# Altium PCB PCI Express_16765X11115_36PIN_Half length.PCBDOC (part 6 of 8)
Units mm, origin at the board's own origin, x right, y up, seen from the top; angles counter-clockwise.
Board outline 178 x 110.97 mm, 10 copper layers (Top Layer, Int1 (GND), Int2 (Sign), Int3 (Sign), Int4 (PWR), Int5 (GND), Int6 (Sign), Int7 (Sign), Int8 (GND), Bottom Layer), stack 1.429 mm thick; 528 components, 525 nets, 2272 pads, 1491 vias.
Unrouted connection lines stored in the file: 373.
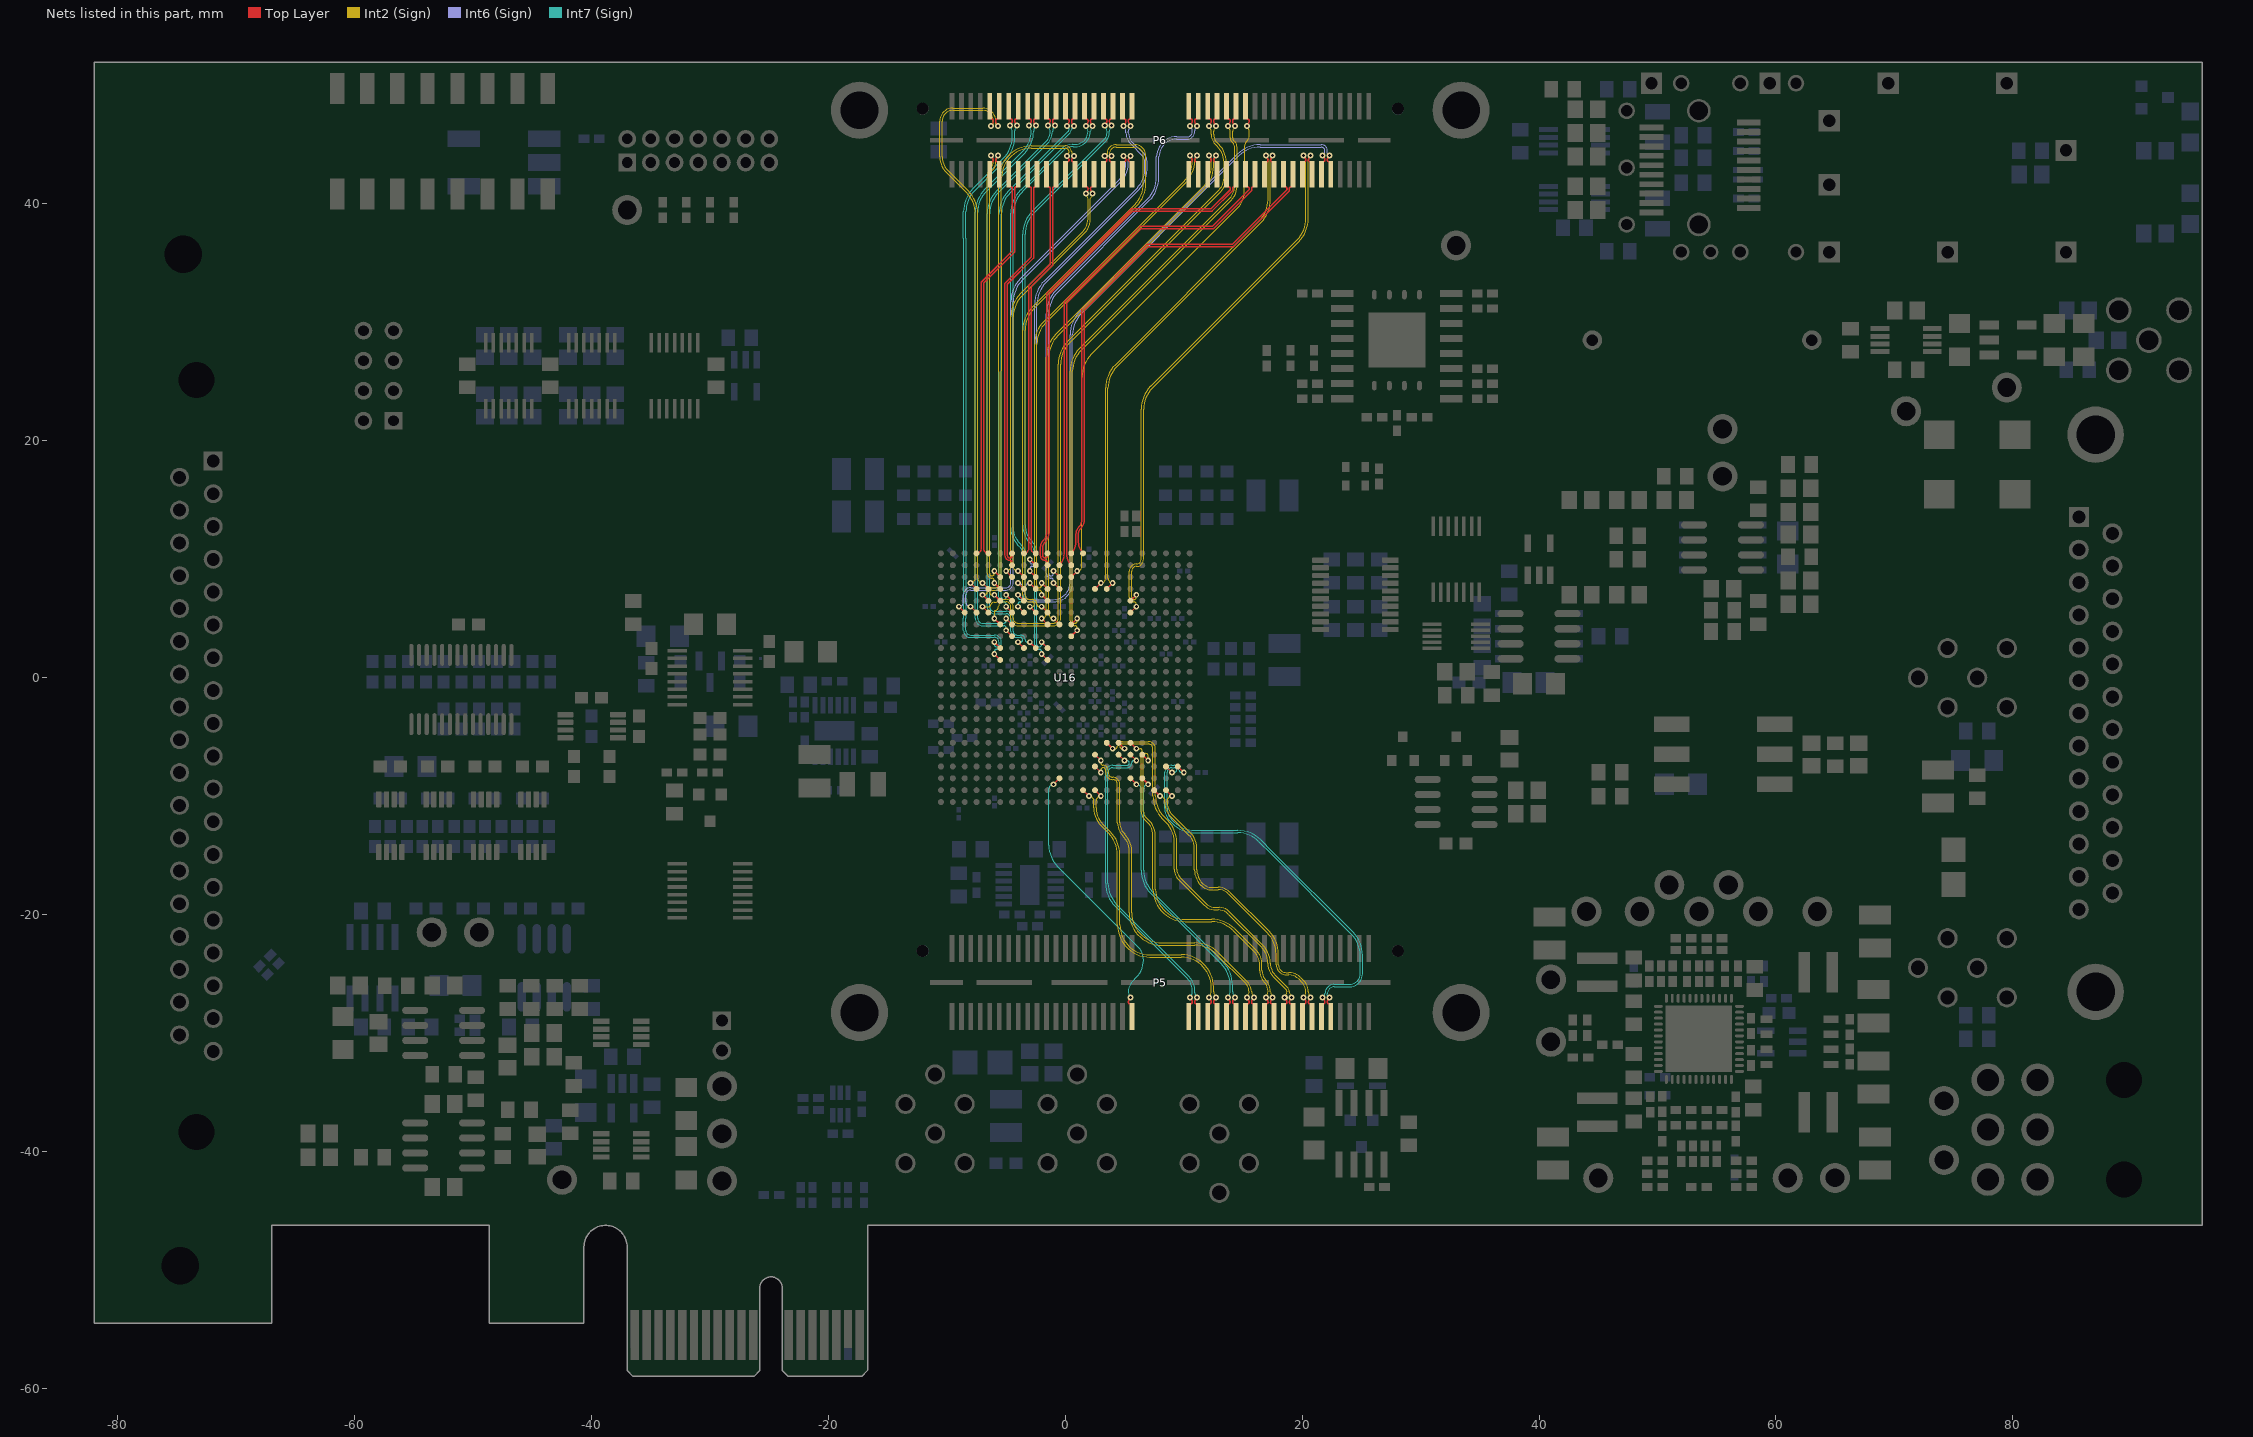
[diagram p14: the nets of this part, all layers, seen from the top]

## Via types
v1: diameter 0.483, hole 0.254, Top Layer to Bottom Layer, tented both sides, 740 vias
v2: diameter 0.508, hole 0.254, Top Layer to Bottom Layer, tented both sides, 302 vias
v3: diameter 0.406, hole 0.254, Top Layer to Bottom Layer, tented both sides, 267 vias
v4: diameter 0.305, hole 0.152, Top Layer to Bottom Layer, tented both sides, 95 vias
v5: diameter 0.5, hole 0.254, Top Layer to Bottom Layer, tented both sides, 50 vias
v6: diameter 0.45, hole 0.254, Top Layer to Bottom Layer, tented both sides, 23 vias
v7: diameter 0.6, hole 0.254, Top Layer to Bottom Layer, tented both sides, 14 vias

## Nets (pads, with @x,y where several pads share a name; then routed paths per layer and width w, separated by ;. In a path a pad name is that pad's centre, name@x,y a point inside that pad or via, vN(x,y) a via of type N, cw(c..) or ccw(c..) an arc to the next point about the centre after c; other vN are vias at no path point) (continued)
S17_32.S24_P: P5.39 U16.L3 | length 24.3
  Top Layer w0.127: v1(-1,-9) U16.L3@-0.5,-8.5 ; v2(5.512,-27) cw(c5.333,-27) 5.46,-27.127 5.417,-27.17 ccw(c5.647,-27.4) 5.322,-27.4 ccw(c5.474,-27.4) 5.366,-27.508 ccw(c5.438,-27.436) 5.438,-27.538 cw(c5.438,-27.64) 5.51,-27.568 5.55,-27.608 cw(c5.382,-27.776) 5.62,-27.776 P5.39@5.62,-28.605
  Int7 (Sign) w0.076: v1(-1,-9) ccw(c-1,-9.398) -1.398,-9.398 -1.398,-14.149 ccw(c1.142,-14.149) -0.654,-15.946 6.152,-22.752 cw(c5.063,-23.841) 6.603,-23.841 6.603,-23.844 cw(c4.544,-23.844) 6,-25.3 5.719,-25.581 ccw(c6.678,-26.54) 5.322,-26.54 ccw(c5.803,-26.54) 5.463,-26.88 cw(c5.343,-27) v2(5.512,-27)
S17_32.S25_N: P5.43 U16.U5 | length 27.4
  Top Layer w0.127: U16.U5@5.5,-6.5 v1(6,-7) ; v2(11.112,-27) cw(c10.932,-27) 11.059,-27.127 11.017,-27.17 ccw(c11.247,-27.4) 10.922,-27.4 ccw(c11.074,-27.4) 10.966,-27.508 ccw(c11.038,-27.436) 11.038,-27.538 cw(c11.038,-27.64) 11.11,-27.568 11.15,-27.608 cw(c10.981,-27.776) 11.22,-27.776 P5.43@11.22,-28.605
  Int7 (Sign) w0.076: v1(6,-7) 5.802,-7 ccw(c5.802,-7.2) 5.602,-7.2 cw(c5.198,-7.2) 5.198,-7.603 4,-7.603 ccw(c4,-8.003) 3.6,-8.003 3.6,-17.361 ccw(c6.14,-17.361) 4.344,-19.157 10.445,-25.257 cw(c9.293,-26.409) 10.922,-26.409 10.922,-26.6 ccw(c11.258,-26.6) 11.02,-26.838 11.063,-26.88 cw(c10.943,-27) v2(11.112,-27)
S17_32.S25_P: P5.41 U16.T5 | length 27.4
  Top Layer w0.127: U16.T5@4.5,-6.5 v1(5,-7) ; P5.41@10.42,-28.605 10.42,-27.776 cw(c10.658,-27.776) 10.49,-27.608 10.53,-27.568 cw(c10.602,-27.64) 10.602,-27.538 ccw(c10.602,-27.436) 10.674,-27.508 ccw(c10.566,-27.4) 10.718,-27.4 ccw(c10.393,-27.4) 10.623,-27.17 10.58,-27.127 cw(c10.707,-27) v2(10.528,-27)
  Int7 (Sign) w0.076: v1(5,-7) 5.198,-7 cw(c5.198,-7.2) 5.398,-7.2 cw(c5.198,-7.2) 5.198,-7.4 4,-7.4 ccw(c4,-8.003) 3.397,-8.003 3.397,-17.361 ccw(c6.139,-17.361) 4.2,-19.3 10.3,-25.4 cw(c9.29,-26.41) 10.718,-26.41 10.718,-26.6 cw(c10.382,-26.6) 10.62,-26.838 10.577,-26.88 ccw(c10.697,-27) v2(10.528,-27)
S17_32.S26_N: P5.45 U16.N2 | length 26.1
  Top Layer w0.127: U16.N2@1.5,-9.5 v1(2,-10) ; P5.45@12.02,-28.605 12.02,-27.776 cw(c12.258,-27.776) 12.09,-27.608 12.13,-27.568 cw(c12.202,-27.64) 12.202,-27.538 ccw(c12.202,-27.436) 12.274,-27.508 ccw(c12.166,-27.4) 12.318,-27.4 ccw(c11.993,-27.4) 12.223,-27.17 12.18,-27.127 cw(c12.307,-27) v2(12.128,-27)
  Int2 (Sign) w0.076: v1(2,-10) cw(c2,-10.398) 2.398,-10.398 2.398,-11.001 ccw(c4.535,-11.001) 3.024,-12.512 3.656,-13.143 cw(c1.86,-14.939) 4.4,-14.939 4.4,-20.857 ccw(c7.143,-20.857) 7.143,-23.6 9.778,-23.6 cw(c9.778,-26.14) 12.318,-26.14 12.318,-26.54 cw(c11.837,-26.54) 12.177,-26.88 ccw(c12.297,-27) v2(12.128,-27)
S17_32.S26_P: P5.47 U16.P2 | length 26.1
  Top Layer w0.127: U16.P2@2.5,-9.5 v1(3,-10) ; v2(12.712,-27) cw(c12.532,-27) 12.659,-27.127 12.617,-27.17 ccw(c12.847,-27.4) 12.521,-27.4 ccw(c12.673,-27.4) 12.566,-27.508 ccw(c12.638,-27.436) 12.638,-27.538 cw(c12.638,-27.64) 12.71,-27.568 12.75,-27.608 cw(c12.581,-27.776) 12.82,-27.776 P5.47@12.82,-28.605
  Int2 (Sign) w0.076: v1(3,-10) ccw(c3,-10.398) 2.602,-10.398 2.602,-11 ccw(c4.537,-11) 3.168,-12.368 3.802,-13.002 cw(c1.866,-14.937) 4.603,-14.937 4.603,-20.857 ccw(c7.143,-20.857) 7.143,-23.397 9.778,-23.397 cw(c9.778,-26.14) 12.521,-26.14 12.521,-26.54 ccw(c13.003,-26.54) 12.662,-26.88 cw(c12.543,-27) v2(12.712,-27)
S17_32.S27_N: P5.51 U16.V3 | length 23.7
  Top Layer w0.127: U16.V3@6.5,-8.5 v1(7,-9) ; v2(14.312,-27) cw(c14.132,-27) 14.259,-27.127 14.217,-27.17 ccw(c14.447,-27.4) 14.122,-27.4 ccw(c14.274,-27.4) 14.166,-27.508 ccw(c14.238,-27.436) 14.238,-27.538 cw(c14.238,-27.64) 14.31,-27.568 14.35,-27.608 cw(c14.181,-27.776) 14.42,-27.776 P5.51@14.42,-28.605
  Int7 (Sign) w0.076: v1(7,-9) ccw(c7,-9.398) 6.602,-9.398 6.602,-16.262 ccw(c9.142,-16.262) 7.346,-18.058 13.319,-24.031 cw(c11.38,-25.97) 14.122,-25.97 14.122,-26.54 ccw(c14.603,-26.54) 14.262,-26.88 cw(c14.143,-27) v2(14.312,-27)
S17_32.S27_P: P5.49 U16.U3 | length 23.7
  Top Layer w0.127: U16.U3@5.5,-8.5 v1(6,-9) ; P5.49@13.62,-28.605 13.62,-27.776 cw(c13.858,-27.776) 13.69,-27.608 13.73,-27.568 cw(c13.802,-27.64) 13.802,-27.538 ccw(c13.802,-27.436) 13.874,-27.508 ccw(c13.766,-27.4) 13.918,-27.4 ccw(c13.593,-27.4) 13.823,-27.17 13.78,-27.127 cw(c13.907,-27) v2(13.728,-27)
  Int7 (Sign) w0.076: v1(6,-9) cw(c6,-9.398) 6.398,-9.398 6.398,-16.263 ccw(c9.14,-16.263) 7.201,-18.201 13.174,-24.174 cw(c11.378,-25.97) 13.918,-25.97 13.918,-26.54 cw(c13.437,-26.54) 13.777,-26.88 ccw(c13.897,-27) v2(13.728,-27)
S17_32.S28_N: P5.53 U16.P4 | length 30.2
  Top Layer w0.127: U16.P4@2.5,-7.5 v1(3,-8) ; P5.53@15.22,-28.605 15.22,-27.776 cw(c15.458,-27.776) 15.289,-27.608 15.33,-27.568 cw(c15.402,-27.64) 15.402,-27.538 ccw(c15.402,-27.436) 15.474,-27.508 ccw(c15.366,-27.4) 15.518,-27.4 ccw(c15.193,-27.4) 15.423,-27.17 15.38,-27.127 cw(c15.507,-27) v2(15.328,-27)
  Int2 (Sign) w0.076: v1(3,-8) 3,-7.802 cw(c3.2,-7.802) 3.2,-7.602 cw(c3.2,-7.802) 3.4,-7.802 3.4,-8.003 ccw(c4,-8.003) 4,-8.603 4.003,-8.603 cw(c4.003,-9) 4.4,-9 4.4,-12.244 ccw(c5.953,-12.244) 4.855,-13.342 cw(c3.539,-14.658) 4.856,-13.344 cw(c3.539,-14.658) 5.4,-14.658 5.4,-19.857 ccw(c8.143,-19.857) 8.143,-22.6 10.948,-22.6 cw(c10.948,-25.14) 12.744,-23.344 15.22,-25.82 cw(c14.499,-26.54) 15.518,-26.54 cw(c15.037,-26.54) 15.377,-26.88 ccw(c15.497,-27) v2(15.328,-27)
S17_32.S28_P: P5.55 U16.P5 | length 30.5
  Top Layer w0.127: U16.P5@2.5,-6.5 v1(3,-7) ; v2(15.912,-27) cw(c15.732,-27) 15.859,-27.127 15.817,-27.17 ccw(c16.046,-27.4) 15.721,-27.4 ccw(c15.873,-27.4) 15.766,-27.508 ccw(c15.838,-27.436) 15.838,-27.538 cw(c15.838,-27.64) 15.91,-27.568 15.95,-27.608 cw(c15.781,-27.776) 16.02,-27.776 P5.55@16.02,-28.605
  Int2 (Sign) w0.076: v1(3,-7) 3,-7.198 ccw(c3.2,-7.198) 3.2,-7.398 cw(c3.2,-7.802) 3.603,-7.802 3.603,-8.003 ccw(c4,-8.003) 4,-8.4 4.003,-8.4 cw(c4.003,-9) 4.603,-9 4.603,-12.242 ccw(c5.958,-12.242) 5,-13.2 5.002,-13.202 cw(c3.549,-14.654) 5.003,-13.203 cw(c3.549,-14.654) 5.603,-14.654 5.603,-19.857 ccw(c8.143,-19.857) 8.143,-22.397 10.949,-22.397 cw(c10.949,-25.138) 12.887,-23.2 15.365,-25.677 cw(c14.504,-26.538) 15.721,-26.538 15.721,-26.54 ccw(c16.203,-26.54) 15.862,-26.88 cw(c15.743,-27) v2(15.912,-27)
S17_32.S29_N: P5.59 U16.V5 | length 30.4
  Top Layer w0.127: U16.V5@6.5,-6.5 v1(7,-7) ; v2(17.512,-27) cw(c17.332,-27) 17.459,-27.127 17.417,-27.17 ccw(c17.647,-27.4) 17.321,-27.4 ccw(c17.474,-27.4) 17.366,-27.508 ccw(c17.438,-27.436) 17.438,-27.538 cw(c17.438,-27.64) 17.51,-27.568 17.55,-27.608 cw(c17.381,-27.776) 17.62,-27.776 P5.59@17.62,-28.605
  Int2 (Sign) w0.076: v1(7,-7) 7,-6.6 ccw(c6.8,-6.6) 6.8,-6.4 ccw(c6.8,-6.6) 6.657,-6.46 ccw(c6.796,-6.598) 6.6,-6.598 6.6,-11.3 ccw(c7.324,-11.3) 6.812,-11.812 7.102,-12.102 ; 7.102,-12.102 cw(c5.893,-13.312) 7.603,-13.312 7.603,-17.857 ccw(c10.143,-17.857) 10.143,-20.397 12.349,-20.397 cw(c12.349,-23.138) 14.287,-21.2 16.187,-23.1 cw(c15.19,-24.097) 16.6,-24.097 16.6,-24.725 ccw(c17.776,-24.725) 16.945,-25.557 cw(c16.035,-26.467) 17.321,-26.467 17.321,-26.54 ccw(c17.803,-26.54) 17.462,-26.88 cw(c17.343,-27) v2(17.512,-27)
S17_32.S29_P: P5.57 U16.U6 | length 30.4
  Top Layer w0.127: U16.U6@5.5,-5.5 v1(6,-6) ; P5.57@16.82,-28.605 16.82,-27.776 cw(c17.058,-27.776) 16.89,-27.608 16.93,-27.568 cw(c17.002,-27.64) 17.002,-27.538 ccw(c17.002,-27.436) 17.074,-27.508 ccw(c16.966,-27.4) 17.118,-27.4 ccw(c16.793,-27.4) 17.023,-27.17 16.98,-27.127 cw(c17.107,-27) v2(16.928,-27)
  Int2 (Sign) w0.076: v1(6,-6) 6.3,-6 cw(c6.3,-6.2) 6.5,-6.2 6.5,-6.29 cw(c6.424,-6.29) 6.491,-6.326 6.464,-6.376 ccw(c6.796,-6.598) 6.397,-6.598 6.397,-6.649 6.397,-11.301 ccw(c7.323,-11.301) 6.668,-11.955 ; 6.668,-11.955 6.956,-12.244 cw(c5.885,-13.315) 7.4,-13.315 7.4,-17.857 ccw(c10.143,-17.857) 10.143,-20.6 12.348,-20.6 cw(c12.348,-23.14) 14.144,-21.344 16.041,-23.241 cw(c15.182,-24.1) 16.397,-24.1 16.397,-24.727 ccw(c17.773,-24.727) 16.8,-25.7 cw(c16.032,-26.468) 17.118,-26.468 17.118,-26.54 cw(c16.637,-26.54) 16.977,-26.88 ccw(c17.097,-27) v2(16.928,-27)
S17_32.S30_N: P5.61 U16.T6 | length 32.1
  Top Layer w0.127: U16.T6@4.5,-5.5 v1(5,-6) ; P5.61@18.42,-28.605 18.42,-27.776 cw(c18.658,-27.776) 18.489,-27.608 18.529,-27.568 cw(c18.601,-27.64) 18.601,-27.538 ccw(c18.601,-27.436) 18.673,-27.508 ccw(c18.566,-27.4) 18.718,-27.4 ccw(c18.393,-27.4) 18.623,-27.17 18.58,-27.127 cw(c18.707,-27) v2(18.528,-27)
  Int2 (Sign) w0.076: v1(5,-6) 4.802,-6 cw(c4.802,-5.8) 4.602,-5.8 cw(c4.802,-5.8) 4.802,-5.6 7,-5.6 cw(c7,-6) 7.4,-6 7.4,-9.964 ccw(c10.142,-9.964) 8.203,-11.903 8.5,-12.2 cw(c6.81,-13.89) 9.2,-13.89 9.2,-16.164 ccw(c10.464,-16.164) 9.57,-17.058 ; 9.572,-17.059 11.705,-19.192 ccw(c12.697,-18.199) 12.697,-19.603 12.9,-19.603 cw(c12.9,-20.818) 13.759,-19.959 16.528,-22.728 cw(c15.153,-24.102) 17.097,-24.1 cw(c15.153,-24.102) 17.097,-24.102 ccw(c18.736,-24.102) 17.577,-25.261 18.621,-26.305 cw(c18.385,-26.54) 18.718,-26.54 cw(c18.237,-26.54) 18.577,-26.88 ccw(c18.697,-27) v2(18.528,-27)
S17_32.S30_P: P5.63 U16.R6 | length 32.8
  Top Layer w0.127: U16.R6@3.5,-5.5 v1(4,-6) ; v2(19.112,-27) cw(c18.932,-27) 19.059,-27.127 19.017,-27.17 ccw(c19.246,-27.4) 18.921,-27.4 ccw(c19.073,-27.4) 18.966,-27.508 ccw(c19.038,-27.436) 19.038,-27.538 cw(c19.038,-27.64) 19.11,-27.568 19.15,-27.608 cw(c18.981,-27.776) 19.22,-27.776 P5.63@19.22,-28.605
  Int2 (Sign) w0.076: v1(4,-6) 4.198,-6 ccw(c4.198,-5.8) 4.398,-5.8 cw(c4.802,-5.8) 4.802,-5.397 7,-5.397 cw(c7,-6) 7.603,-6 7.603,-9.964 ccw(c10.143,-9.964) 8.347,-11.76 8.647,-12.059 cw(c6.821,-13.885) 9.403,-13.885 9.403,-16.162 ccw(c10.469,-16.162) 9.715,-16.915 11.846,-19.046 ccw(c12.7,-18.193) 12.7,-19.4 12.984,-19.4 cw(c12.984,-20.615) 13.843,-19.755 16.674,-22.587 cw(c15.163,-24.098) 17.3,-24.098 17.3,-24.1 ccw(c18.741,-24.1) 17.722,-25.119 18.765,-26.162 cw(c18.389,-26.539) 18.921,-26.539 18.921,-26.54 ccw(c19.403,-26.54) 19.062,-26.88 cw(c18.943,-27) v2(19.112,-27)
S17_32.S31_N: P5.67 U16.Y2 | length 25.7
  Top Layer w0.127: U16.Y2@8.5,-9.5 v1(9,-10) ; v2(20.712,-27) cw(c20.532,-27) 20.659,-27.127 20.617,-27.17 ccw(c20.847,-27.4) 20.521,-27.4 ccw(c20.674,-27.4) 20.566,-27.508 ccw(c20.638,-27.436) 20.638,-27.538 cw(c20.638,-27.64) 20.71,-27.568 20.75,-27.608 cw(c20.581,-27.776) 20.82,-27.776 P5.67@20.82,-28.605
  Int2 (Sign) w0.076: v1(9,-10) ccw(c9,-10.398) 8.602,-10.398 8.602,-10.5 ccw(c10.206,-10.5) 9.072,-11.635 10.586,-13.149 cw(c9.338,-14.397) 11.103,-14.397 11.103,-16.201 ccw(c12.799,-16.201) 11.6,-17.4 ccw(c12.324,-16.676) 12.324,-17.7 12.901,-17.7 cw(c12.901,-19.116) 13.902,-18.115 17.198,-21.411 cw(c15.263,-23.346) 18,-23.346 18,-24.245 ccw(c18.651,-24.245) 18.651,-24.897 18.878,-24.897 ; 18.884,-24.897 cw(c18.884,-26.248) 19.839,-25.292 20.123,-25.576 cw(c19.161,-26.538) 20.521,-26.535 cw(c19.161,-26.538) 20.521,-26.538 20.521,-26.54 ccw(c21.003,-26.54) 20.662,-26.88 cw(c20.543,-27) v2(20.712,-27)
S17_32.S31_P: P5.65 U16.W2 | length 25.7
  Top Layer w0.127: U16.W2@7.5,-9.5 v1(8,-10) ; P5.65@20.02,-28.605 20.02,-27.776 cw(c20.258,-27.776) 20.09,-27.608 20.13,-27.568 cw(c20.202,-27.64) 20.202,-27.538 ccw(c20.202,-27.436) 20.274,-27.508 ccw(c20.166,-27.4) 20.318,-27.4 ccw(c19.993,-27.4) 20.223,-27.17 20.18,-27.127 cw(c20.307,-27) v2(20.128,-27)
  Int2 (Sign) w0.076: v1(8,-10) cw(c8,-10.398) 8.398,-10.398 8.398,-10.501 ccw(c10.205,-10.501) 8.928,-11.778 10.441,-13.291 cw(c9.332,-14.4) 10.9,-14.4 10.9,-16.202 ccw(c12.796,-16.202) 11.455,-17.543 11.458,-17.545 ccw(c12.322,-16.68) 12.322,-17.903 12.9,-17.903 cw(c12.9,-19.118) 13.759,-18.259 17.053,-21.553 cw(c15.257,-23.349) 17.797,-23.349 17.797,-24.245 ccw(c18.651,-24.245) 18.651,-25.1 18.878,-25.1 cw(c18.878,-26.262) 19.7,-25.44 19.978,-25.718 cw(c19.156,-26.54) 20.318,-26.54 cw(c19.837,-26.54) 20.177,-26.88 ccw(c20.297,-27) v2(20.128,-27)
S17_32.S32_N: P5.69 U16.AA4 | length 36
  Top Layer w0.127: U16.AA4@9.5,-7.5 v1(10,-8) ; P5.69@21.62,-28.605 21.62,-27.776 cw(c21.858,-27.776) 21.689,-27.608 21.729,-27.568 cw(c21.801,-27.64) 21.801,-27.538 ccw(c21.801,-27.436) 21.873,-27.508 ccw(c21.766,-27.4) 21.918,-27.4 ccw(c21.593,-27.4) 21.823,-27.17 21.78,-27.127 cw(c21.907,-27) v2(21.728,-27)
  Int7 (Sign) w0.076: v1(10,-8) 9.802,-8 cw(c9.802,-7.8) 9.602,-7.8 ccw(c9.198,-7.8) 9.198,-7.397 9,-7.397 ccw(c9,-8) 8.397,-8 8.397,-11.035 ccw(c9.963,-11.035) 8.856,-12.143 9.026,-12.313 ccw(c10.933,-10.406) 10.933,-13.103 14.557,-13.103 cw(c14.557,-15.643) 16.353,-13.847 17.3,-14.794 17.3,-14.8 24.156,-21.656 cw(c22.36,-23.452) 24.9,-23.452 24.9,-25 cw(c24.003,-25) 24.003,-25.897 22.721,-25.897 ccw(c22.721,-26.7) 21.918,-26.7 21.918,-26.809 cw(c21.728,-26.809) v2(21.728,-27)
S17_32.S32_P: P5.71 U16.Y4 | length 35.4
  Top Layer w0.127: U16.Y4@8.5,-7.5 v1(9,-8) ; v2(22.312,-27) cw(c22.132,-27) 22.259,-27.127 22.216,-27.17 ccw(c22.446,-27.4) 22.121,-27.4 ccw(c22.273,-27.4) 22.166,-27.508 ccw(c22.238,-27.436) 22.238,-27.538 cw(c22.238,-27.64) 22.31,-27.568 22.35,-27.608 cw(c22.181,-27.776) 22.42,-27.776 P5.71@22.42,-28.605
  Int7 (Sign) w0.076: v1(9,-8) 9.198,-8 ccw(c9.198,-7.8) 9.398,-7.8 ccw(c9.198,-7.8) 9.198,-7.6 9,-7.6 ccw(c9,-8) 8.6,-8 8.6,-11.034 ccw(c9.966,-11.034) 9,-12 9.169,-12.169 ccw(c10.934,-10.405) 10.934,-12.9 14.558,-12.9 cw(c14.558,-15.641) 16.497,-13.703 17.444,-14.65 17.45,-14.65 24.293,-21.493 cw(c22.336,-23.45) 25.103,-23.45 25.103,-25 cw(c24.003,-25) 24.003,-26.1 22.721,-26.1 ccw(c22.721,-26.7) 22.121,-26.7 22.121,-26.809 ccw(c22.312,-26.809) v2(22.312,-27)
S33_48.S33_N: P6.11 U16.F20 | length 38.8
  Top Layer w0.127: v1(-6,9) U16.F20@-5.5,8.5 ; v2(-5.688,44.1) cw(c-5.867,44.1) -5.74,43.973 -5.796,43.917 ccw(c-5.599,43.72) -5.878,43.72 ccw(c-5.726,43.72) -5.833,43.612 ccw(c-5.761,43.684) -5.761,43.582 cw(c-5.761,43.48) -5.689,43.552 -5.649,43.512 cw(c-5.818,43.344) -5.58,43.344 P6.11@-5.58,42.515
  Int2 (Sign) w0.076: v1(-6,9) -6,8.802 cw(c-6.2,8.802) -6.2,8.602 cw(c-6.2,8.802) -6.4,8.802 -6.4,40.067 -6.4,42.268 cw(c-5.568,42.268) -6.156,42.856 -6.155,42.857 ccw(c-6.824,43.527) -5.878,43.527 -5.878,43.64 cw(c-5.397,43.64) -5.737,43.98 ccw(c-5.857,44.1) v2(-5.688,44.1)
S33_48.S33_P: P6.9 U16.F19 | length 39.1
  Top Layer w0.127: P6.9@-6.38,42.515 -6.38,43.344 cw(c-6.141,43.344) -6.31,43.512 -6.27,43.552 cw(c-6.198,43.48) -6.198,43.582 ccw(c-6.198,43.684) -6.126,43.612 ccw(c-6.233,43.72) -6.081,43.72 ccw(c-6.36,43.72) -6.163,43.917 -6.219,43.973 cw(c-6.092,44.1) v2(-6.272,44.1) ; v1(-6,8) U16.F19@-5.5,7.5
  Int2 (Sign) w0.076: v2(-6.272,44.1) ccw(c-6.103,44.1) -6.222,43.98 cw(c-6.563,43.64) -6.081,43.64 -6.081,43.528 cw(c-6.828,43.528) -6.3,43 ccw(c-5.571,42.269) -6.603,42.269 -6.603,40.068 -6.603,8.802 ccw(c-6.2,8.802) -6.2,8.398 cw(c-6.2,8.198) -6,8.198 v1(-6,8)
S33_48.S34_N: P6.13 U16.D22 | length 33.5
  Top Layer w0.127: U16.D22@-7.5,10.5 ccw(c-7.5,10.898) -7.102,10.898 -7.102,13.156 -7.102,33.398 -4.481,36.019 -4.481,41.322 ccw(c-4.608,41.322) -4.519,41.411 -4.526,41.419 ccw(c-4.598,41.347) -4.598,41.449 cw(c-4.598,41.55) -4.67,41.478 cw(c-4.405,41.744) -4.78,41.744 P6.13@-4.78,42.515
S33_48.S34_P: P6.15 U16.E22 | length 33.5
  Top Layer w0.127: U16.E22@-6.5,10.5 cw(c-6.5,10.898) -6.898,10.898 -6.898,13.156 -6.898,33.314 -4.278,35.934 -4.278,41.322 cw(c-4.151,41.322) -4.241,41.411 -4.234,41.419 cw(c-4.162,41.347) -4.162,41.449 ccw(c-4.162,41.55) -4.09,41.478 ccw(c-4.355,41.744) -3.98,41.744 P6.15@-3.98,42.515
S33_48.S35_N: P6.19 U16.G22 | length 34.1
  Top Layer w0.127: U16.G22@-4.5,10.5 -4.5,10.273 cw(c-4.672,10.273) -4.672,10.102 cw(c-4.672,10.326) -4.896,10.326 -4.896,13.156 -4.896,33.216 -2.678,35.435 -2.678,41.322 cw(c-2.551,41.322) -2.641,41.411 -2.633,41.419 cw(c-2.561,41.347) -2.561,41.449 ccw(c-2.561,41.55) -2.489,41.478 ccw(c-2.755,41.744) -2.488,41.479 -2.449,41.518 ccw(c-2.618,41.687) -2.38,41.687 P6.19@-2.38,42.515
S33_48.S35_P: P6.17 U16.G21 | length 34.7
  Top Layer w0.127: U16.G21@-4.5,9.5 -4.5,9.727 ccw(c-4.672,9.727) -4.672,9.898 cw(c-4.672,10.326) -5.099,10.326 -5.099,13.156 -5.099,33.301 -2.881,35.519 -2.881,41.322 ccw(c-3.008,41.322) -2.918,41.411 -2.926,41.419 ccw(c-2.998,41.347) -2.998,41.449 cw(c-2.998,41.55) P6.17@-3.07,41.478 ; P6.17@-3.18,42.515 P6.17@-3.18,41.744 ; P6.17@-3.18,41.744 ccw(c-2.805,41.744) P6.17@-3.07,41.478 ; P6.17@-3.18,41.744 -3.18,41.687 ccw(c-2.941,41.687) -3.11,41.518 P6.17@-3.07,41.478
S33_48.S36_N: P6.21 U16.H22 | length 33.1
  Top Layer w0.127: U16.H22@-3.5,10.5 ccw(c-3.5,10.898) -3.102,10.897 -3.102,13.156 -3.102,33.098 -1.281,34.919 -1.281,41.311 ccw(c-1.434,41.311) -1.326,41.419 ccw(c-1.398,41.347) -1.398,41.449 cw(c-1.398,41.55) -1.47,41.478 -1.51,41.518 cw(c-1.341,41.687) -1.58,41.687 P6.21@-1.58,42.515
S33_48.S36_P: P6.23 U16.J22 | length 33.1
  Top Layer w0.127: U16.J22@-2.5,10.5 cw(c-2.5,10.898) -2.898,10.898 -2.898,13.156 -2.898,33.014 -1.078,34.834 -1.078,41.311 cw(c-0.926,41.311) -1.034,41.419 cw(c-0.962,41.347) -0.962,41.449 ccw(c-0.962,41.55) -0.89,41.478 -0.85,41.518 ccw(c-1.018,41.687) -0.78,41.687 P6.23@-0.78,42.515
S33_48.S37_N: P6.27 U16.E18 | length 46.7
  Top Layer w0.127: v1(-7,7) U16.E18@-6.5,6.5 ; 0.569,43.833 ccw(c0.682,43.72) 0.522,43.72 ccw(c0.674,43.72) 0.566,43.612 ccw(c0.638,43.684) 0.638,43.582 cw(c0.638,43.48) 0.71,43.552 0.751,43.512 cw(c0.582,43.344) 0.82,43.344 P6.27@0.82,42.515
  Int2 (Sign) w0.076: v1(-7,7) -6.802,7 ccw(c-6.802,7.2) -6.602,7.2 cw(c-6.198,7.2) -6.198,7.603 -5.9,7.603 ccw(c-5.9,7.903) -5.6,7.903 -5.6,25.832 -5.603,25.835 -5.603,42.164 cw(c-2.864,42.164) -2.864,44.903 0.011,44.903 cw(c0.011,44.393) 0.522,44.393 ; 0.522,44.392 ccw(c0.716,44.392) 0.579,44.255 v2@0.663,44.17 ; v2@0.663,44.17 cw(c0.543,44.051) v2(0.712,44.051)
S33_48.S37_P: P6.25 U16.F18 | length 46.2
  Top Layer w0.127: v1(-6,7) U16.F18@-5.5,6.5 ; P6.25@0.02,42.515 0.02,43.344 cw(c0.259,43.344) 0.09,43.512 0.13,43.552 cw(c0.202,43.48) 0.202,43.582 ccw(c0.202,43.684) 0.274,43.612 ccw(c0.167,43.72) 0.319,43.72 ccw(c0.159,43.72) 0.272,43.833
  Int2 (Sign) w0.076: v1(-6,7) -6.198,7 cw(c-6.198,7.2) -6.398,7.2 cw(c-6.198,7.2) -6.198,7.4 -5.9,7.4 ccw(c-5.9,7.903) -5.397,7.903 -5.397,25.931 -5.4,25.934 -5.4,39.5 ; -5.4,39.4 -5.4,39.5 ; v2(0.128,44.051) cw(c0.297,44.051) 0.178,44.17 0.262,44.254 ccw(c0.125,44.392) 0.319,44.392 ccw(c0.01,44.392) 0.01,44.7 -2.86,44.7 ccw(c-2.86,42.16) -5.4,42.16 -5.4,39.5
S33_48.S38_N: P6.29 U16.G20 | length 37.2
  Top Layer w0.127: v1(-5,9) U16.G20@-4.5,8.5 ; P6.29@1.62,42.515 1.62,41.687 ccw(c1.859,41.687) 1.69,41.518 1.73,41.478 ccw(c1.802,41.55) 1.802,41.449 cw(c1.802,41.347) 1.874,41.419 cw(c1.766,41.311) 1.919,41.311 1.919,41.3 cw(c1.593,41.3) 1.823,41.07 1.781,41.027 ccw(c1.908,40.9) v2(1.728,40.9)
  Int2 (Sign) w0.076: v1(-5,9) ccw(c-5,9.398) -4.602,9.398 -4.602,30.463 cw(c-1.861,30.463) -4.602,30.467 cw(c-1.861,30.463) -3.799,32.401 1.467,37.667 ccw(c0.376,38.757) 1.919,38.757 1.919,40.44 ccw(c1.437,40.44) 1.778,40.78 cw(c1.897,40.9) v2(1.728,40.9)
S33_48.S38_P: P6.31 U16.H20 | length 37.2
  Top Layer w0.127: v1(-4,9) U16.H20@-3.5,8.5 ; v2(2.312,40.9) ccw(c2.133,40.9) 2.26,41.027 2.217,41.07 cw(c2.447,41.3) 2.122,41.3 2.122,41.311 cw(c2.274,41.311) 2.166,41.419 cw(c2.238,41.347) 2.238,41.449 ccw(c2.238,41.55) 2.31,41.478 2.35,41.518 ccw(c2.182,41.687) 2.42,41.687 P6.31@2.42,42.515
  Int2 (Sign) w0.076: v1(-4,9) cw(c-4,9.398) -4.398,9.398 -4.398,30.462 cw(c-1.858,30.462) -3.654,32.258 1.613,37.526 ccw(c0.387,38.753) 2.122,38.753 2.122,40.44 cw(c2.603,40.44) 2.263,40.78 ccw(c2.143,40.9) v2(2.312,40.9)
S33_48.S39_N: P6.35 U16.J17 | length 49.4
  Top Layer w0.127: v1(-3,6) U16.J17@-2.5,5.5 ; v2(3.912,44.051) cw(c3.733,44.051) 3.86,43.924 3.769,43.833 ccw(c3.882,43.72) 3.722,43.72 ccw(c3.874,43.72) 3.766,43.612 ccw(c3.838,43.684) 3.838,43.582 cw(c3.838,43.48) 3.91,43.552 3.951,43.512 cw(c3.782,43.344) 4.02,43.344 P6.35@4.02,42.515
  Int2 (Sign) w0.076: v1(-3,6) -2.802,6 ccw(c-2.802,6.2) -2.602,6.2 ccw(c-2.802,6.2) -2.802,6.4 -3.003,6.4 cw(c-3.003,7) -3.603,7 -3.603,29.349 cw(c-0.863,29.349) -3.603,29.353 cw(c-0.863,29.349) -2.8,31.287 5.856,39.943 ccw(c4.06,41.739) 6.6,41.739 6.6,44.056 ; v2(3.912,44.051) cw(c3.912,44.241) 3.722,44.241 cw(c4.281,44.241) 4.281,44.8 5.856,44.8 cw(c5.856,44.056) 6.6,44.056 ; 6.6,44.1 6.6,44.056
S33_48.S39_P: P6.33 U16.K17 | length 50.1
  Top Layer w0.127: v1(-2,6) U16.K17@-1.5,5.5 ; P6.33@3.22,42.515 3.22,43.344 cw(c3.459,43.344) 3.29,43.512 3.33,43.552 cw(c3.402,43.48) 3.402,43.582 ccw(c3.402,43.684) 3.474,43.612 ccw(c3.367,43.72) 3.519,43.72 ccw(c3.359,43.72) 3.472,43.833 3.381,43.924 cw(c3.508,44.051) v2(3.328,44.051)
  Int2 (Sign) w0.076: v1(-2,6) -2.198,6 cw(c-2.198,6.2) -2.398,6.2 ccw(c-2.802,6.2) -2.802,6.603 -3.003,6.603 cw(c-3.003,7) -3.4,7 -3.4,29.348 cw(c-0.86,29.348) -2.656,31.144 6,39.8 ccw(c4.063,41.738) 6.002,39.802 ccw(c4.063,41.738) 6.803,41.738 6.803,44.056 ; v2(3.328,44.051) ccw(c3.328,44.241) 3.519,44.241 cw(c4.281,44.241) 4.281,45.003 5.856,45.003 cw(c5.856,44.056) 6.803,44.056 ; 6.803,44.1 6.803,44.056
S33_48.S40_N: P6.37 U16.C17 | length 48.2
  Top Layer w0.127: v1(-9,6) U16.C17@-8.5,5.5 ; P6.37@4.82,42.515 4.82,43.344 cw(c5.059,43.344) 4.89,43.512 4.93,43.552 cw(c5.002,43.48) 5.002,43.582 ccw(c5.002,43.684) 5.074,43.612 ccw(c4.966,43.72) 5.118,43.72 ccw(c4.958,43.72) 5.072,43.833 ; v2(4.928,44.051) ccw(c5.108,44.051) 4.981,43.924 5.072,43.833
  Int6 (Sign) w0.076: v1(-9,6) ccw(c-9,6.398) -8.602,6.398 -8.602,7 cw(c-8,7) -8,7.602 -4.998,7.602 ccw(c-4.998,8) -4.6,8 -4.6,31.752 cw(c-1.859,31.752) -3.798,33.689 ; -3.797,33.69 4.556,42.044 ccw(c3.199,43.401) 5.118,43.401 5.118,43.591 ccw(c4.637,43.591) 4.978,43.931 cw(c5.097,44.051) v2(4.928,44.051)
S33_48.S40_P: P6.39 U16.D17 | length 48.2
  Top Layer w0.127: v1(-8,6) U16.D17@-7.5,5.5 ; v2(5.512,44.051) cw(c5.333,44.051) 5.46,43.924 5.369,43.833 ccw(c5.482,43.72) 5.322,43.72 ccw(c5.474,43.72) 5.366,43.612 ccw(c5.438,43.684) 5.438,43.582 cw(c5.438,43.48) 5.51,43.552 5.55,43.512 cw(c5.382,43.344) 5.62,43.344 P6.39@5.62,42.515
  Int6 (Sign) w0.076: v1(-8,6) cw(c-8,6.398) -8.398,6.398 -8.398,7 cw(c-8,7) -8,7.398 -4.998,7.398 ccw(c-4.998,8) -4.397,8 -4.397,31.751 cw(c-1.857,31.751) -3.653,33.547 4.702,41.902 ccw(c3.207,43.398) 5.322,43.398 5.322,43.591 cw(c5.803,43.591) 5.463,43.931 ccw(c5.343,44.051) v2(5.512,44.051)
S33_48.S41_N: P6.43 U16.K19 | length 45.8
  Top Layer w0.127: v1(-2,8) U16.K19@-1.5,7.5 ; v2(11.112,44.1) cw(c10.932,44.1) 11.059,43.973 11.003,43.917 ccw(c11.201,43.72) 10.922,43.72 ccw(c11.074,43.72) 10.966,43.612 ccw(c11.038,43.684) 11.038,43.582 cw(c11.038,43.48) 11.11,43.552 11.15,43.512 cw(c10.981,43.344) 11.22,43.344 P6.43@11.22,42.515 P6.43@11.22,41.687
  Int2 (Sign) w0.076: v1(-2,8) -2,7.802 cw(c-2.2,7.802) -2.2,7.602 cw(c-2.2,7.802) -2.4,7.802 -2.4,28.161 cw(c0.14,28.161) -1.656,29.957 10.14,41.753 ccw(c8.254,43.639) 10.922,43.639 ; 10.922,43.64 cw(c11.403,43.64) 11.063,43.98 ccw(c10.943,44.1) v2(11.112,44.1)
S33_48.S41_P: P6.41 U16.K18 | length 46.1
  Top Layer w0.127: v1(-2,7) U16.K18@-1.5,6.5 ; P6.41@10.42,41.687 P6.41@10.42,42.515 10.42,43.344 cw(c10.658,43.344) 10.49,43.512 10.53,43.552 cw(c10.602,43.48) 10.602,43.582 ccw(c10.602,43.684) 10.674,43.612 ccw(c10.566,43.72) 10.718,43.72 ccw(c10.439,43.72) 10.637,43.917 10.58,43.973 cw(c10.707,44.1) v2(10.528,44.1)
  Int2 (Sign) w0.076: v1(-2,7) -2,7.198 ccw(c-2.2,7.198) -2.2,7.398 cw(c-2.2,7.802) -2.603,7.802 -2.603,28.162 cw(c0.137,28.162) -1.8,30.1 ; -1.8,30.1 9.996,41.896 ccw(c8.252,43.64) 10.718,43.64 ccw(c10.237,43.64) 10.577,43.98 cw(c10.697,44.1) v2(10.528,44.1)
S33_48.S42_N: P6.45 U16.K16 | length 48.2
  Top Layer w0.127: v1(-2,5) U16.K16@-1.5,4.5 ; P6.45@12.02,41.687 P6.45@12.02,42.515 12.02,43.344 cw(c12.258,43.344) 12.09,43.512 12.13,43.552 cw(c12.202,43.48) 12.202,43.582 ccw(c12.202,43.684) 12.274,43.612 ccw(c12.166,43.72) 12.318,43.72 ccw(c12.039,43.72) 12.237,43.917 12.18,43.973 cw(c12.307,44.1) v2(12.128,44.1)
  Int2 (Sign) w0.076: v1(-2,5) ccw(c-2,5.398) -1.602,5.398 -1.602,27.063 cw(c1.139,27.063) -0.799,29.001 11.574,41.374 ccw(c9.778,43.17) 12.318,43.17 12.318,43.64 ccw(c11.837,43.64) 12.177,43.98 cw(c12.297,44.1) v2(12.128,44.1)
S33_48.S42_P: P6.47 U16.L16 | length 48.2
  Top Layer w0.127: v1(-1,5) U16.L16@-0.5,4.5 ; v2(12.712,44.1) cw(c12.532,44.1) 12.659,43.973 12.603,43.917 ccw(c12.8,43.72) 12.521,43.72 ccw(c12.673,43.72) 12.566,43.612 ccw(c12.638,43.684) 12.638,43.582 cw(c12.638,43.48) 12.71,43.552 12.75,43.512 cw(c12.581,43.344) 12.82,43.344 P6.47@12.82,42.515 P6.47@12.82,41.687
  Int2 (Sign) w0.076: v1(-1,5) cw(c-1,5.398) -1.398,5.398 -1.398,27.062 cw(c1.142,27.062) -0.654,28.858 11.72,41.233 ccw(c9.787,43.166) 12.521,43.166 12.521,43.64 cw(c13.003,43.64) 12.662,43.98 ccw(c12.543,44.1) v2(12.712,44.1)
S33_48.S43_N: P6.51 U16.K22 | length 43.7
  Top Layer w0.127: U16.K22@-1.5,10.5 -1.5,10.301 cw(c-1.699,10.301) -1.699,10.102 cw(c-1.699,10.3) -1.898,10.3 -1.898,11.008 cw(c-1.283,11.008) -1.718,11.443 -1.699,11.462 ccw(c-2.478,12.241) -1.376,12.241 -1.376,13.156 -1.376,32.336 5.684,39.397 12.397,39.397 14.122,41.122 14.122,41.311 cw(c14.274,41.311) 14.166,41.419 cw(c14.238,41.347) 14.238,41.449 ccw(c14.238,41.55) 14.31,41.478 14.35,41.518 ccw(c14.181,41.687) 14.42,41.687 P6.51@14.42,42.515
S33_48.S43_P: P6.49 U16.K21 | length 44
  Top Layer w0.127: U16.K21@-1.5,9.5 -1.5,9.699 ccw(c-1.699,9.699) -1.699,9.898 cw(c-1.699,10.3) -2.101,10.3 -2.101,11.009 cw(c-1.283,11.009) -1.862,11.587 -1.843,11.606 ccw(c-2.479,12.241) -1.579,12.241 -1.579,13.156 -1.579,32.421 5.6,39.6 12.312,39.6 13.918,41.206 13.918,41.311 ccw(c13.766,41.311) 13.874,41.419 ccw(c13.802,41.347) 13.802,41.449 cw(c13.802,41.55) 13.73,41.478 13.69,41.518 cw(c13.858,41.687) 13.62,41.687 P6.49@13.62,42.515
S33_48.S44_N: P6.53 U16.L21 | length 43.3
  Top Layer w0.127: U16.L21@-0.5,9.5 ccw(c-1.462,10.462) -0.102,10.462 -0.102,13.156 -0.102,31.698 6.3,38.1 12.412,38.1 15.518,41.206 15.518,41.311 ccw(c15.366,41.311) 15.474,41.419 ccw(c15.402,41.347) 15.402,41.449 cw(c15.402,41.55) 15.33,41.478 15.289,41.518 cw(c15.458,41.687) 15.22,41.687 P6.53@15.22,42.515
S33_48.S44_P: P6.55 U16.M21 | length 43.3
  Top Layer w0.127: U16.M21@0.5,9.5 cw(c1.462,10.462) 0.102,10.462 0.102,13.156 0.102,31.614 6.384,37.897 12.496,37.897 15.721,41.122 15.721,41.311 cw(c15.873,41.311) 15.766,41.419 cw(c15.838,41.347) 15.838,41.449 ccw(c15.838,41.55) 15.91,41.478 15.95,41.518 ccw(c15.781,41.687) 16.02,41.687 P6.55@16.02,42.515
S33_48.S45_N: P6.59 U16.R19 | length 45.2
  Top Layer w0.127: U16.R19@3.5,7.5 v1(4,8) ; v2(17.512,44.1) cw(c17.332,44.1) 17.459,43.973 17.403,43.917 ccw(c17.6,43.72) 17.321,43.72 ccw(c17.474,43.72) 17.366,43.612 ccw(c17.438,43.684) 17.438,43.582 cw(c17.438,43.48) 17.51,43.552 17.55,43.512 cw(c17.381,43.344) 17.62,43.344 P6.59@17.62,42.515 P6.59@17.62,41.687
  Int2 (Sign) w0.076: v1(4,8) cw(c4,8.398) 3.602,8.398 3.602,13.1 ccw(c3.398,13.1) 3.6,13.122 cw(c3.676,13.13) 3.6,13.129 3.6,13.156 3.6,13.184 3.6,24.461 cw(c6.14,24.461) 4.344,26.257 16.519,38.431 ccw(c14.581,40.369) 17.321,40.369 17.321,43.64 cw(c17.803,43.64) 17.462,43.98 ccw(c17.343,44.1) v2(17.512,44.1)
S33_48.S45_P: P6.57 U16.P19 | length 45.2
  Top Layer w0.127: U16.P19@2.5,7.5 v1(3,8) ; P6.57@16.82,41.687 P6.57@16.82,42.515 16.82,43.344 cw(c17.058,43.344) 16.89,43.512 16.93,43.552 cw(c17.002,43.48) 17.002,43.582 ccw(c17.002,43.684) 17.074,43.612 ccw(c16.966,43.72) 17.118,43.72 ccw(c16.839,43.72) 17.037,43.917 16.98,43.973 cw(c17.107,44.1) v2(16.928,44.1)
  Int2 (Sign) w0.076: v1(3,8) ccw(c3,8.398) 3.398,8.398 3.398,13.1 3.397,13.1 3.397,24.462 cw(c6.137,24.462) 4.2,26.4 16.374,38.574 ccw(c14.578,40.37) 17.118,40.37 17.118,43.64 ccw(c16.637,43.64) 16.977,43.98 cw(c17.097,44.1) v2(16.928,44.1)
S33_48.S46_N: P6.61 U16.M22 | length 43.8
  Top Layer w0.127: U16.M22@0.5,10.5 ccw(c-0.462,11.462) 0.898,11.462 0.898,12.123 cw(c1.774,12.123) 1.155,12.742 1.156,12.744 ccw(c0.568,13.332) 1.4,13.332 1.4,31.1 6.9,36.6 14.112,36.6 18.718,41.206 18.718,41.311 ccw(c18.566,41.311) 18.673,41.419 ccw(c18.601,41.347) 18.601,41.449 cw(c18.601,41.55) 18.529,41.478 18.489,41.518 cw(c18.658,41.687) 18.42,41.687 P6.61@18.42,42.515
S33_48.S46_P: P6.63 U16.N22 | length 43.8
  Top Layer w0.127: U16.N22@1.5,10.5 cw(c2.462,11.462) 1.102,11.462 1.102,12.121 cw(c1.779,12.121) 1.3,12.6 1.303,12.603 ccw(c0.577,13.328) 1.603,13.328 1.603,31.016 6.984,36.397 14.196,36.397 18.921,41.122 18.921,41.311 cw(c19.073,41.311) 18.966,41.419 cw(c19.038,41.347) 19.038,41.449 ccw(c19.038,41.55) 19.11,41.478 19.15,41.518 ccw(c18.981,41.687) 19.22,41.687 P6.63@19.22,42.515
S33_48.S47_N: P6.67 U16.U18 | length 47.6
  Top Layer w0.127: U16.U18@5.5,6.5 v1(6,7) ; v2(20.712,44.1) cw(c20.532,44.1) 20.659,43.973 20.603,43.917 ccw(c20.8,43.72) 20.521,43.72 ccw(c20.674,43.72) 20.566,43.612 ccw(c20.638,43.684) 20.638,43.582 cw(c20.638,43.48) 20.71,43.552 20.75,43.512 cw(c20.581,43.344) 20.82,43.344 P6.67@20.82,42.515 P6.67@20.82,41.687
  Int2 (Sign) w0.076: v1(6,7) 6,6.802 cw(c5.8,6.802) 5.8,6.602 cw(c5.8,6.802) 5.6,6.802 5.6,9 cw(c6,9) 6,9.4 6.003,9.4 ccw(c6.003,10) 6.603,10 6.603,22.664 cw(c9.143,22.664) 7.344,24.457 cw(c9.143,22.664) 7.347,24.46 19.719,36.831 ccw(c17.781,38.769) 20.521,38.769 20.521,43.64 cw(c21.003,43.64) 20.662,43.98 ccw(c20.543,44.1) v2(20.712,44.1)
S33_48.S47_P: P6.65 U16.U17 | length 47.9
  Top Layer w0.127: U16.U17@5.5,5.5 v1(6,6) ; P6.65@20.02,41.687 P6.65@20.02,42.515 20.02,43.344 cw(c20.258,43.344) 20.09,43.512 20.13,43.552 cw(c20.202,43.48) 20.202,43.582 ccw(c20.202,43.684) 20.274,43.612 ccw(c20.166,43.72) 20.318,43.72 ccw(c20.039,43.72) 20.237,43.917 20.18,43.973 cw(c20.307,44.1) v2(20.128,44.1)
  Int2 (Sign) w0.076: v1(6,6) 6,6.198 ccw(c5.8,6.198) 5.8,6.398 cw(c5.8,6.802) 5.397,6.802 5.397,9 cw(c6,9) 6,9.603 6.003,9.603 ccw(c6.003,10) 6.4,10 6.4,22.682 cw(c9.099,22.682) 7.19,24.59 ; 7.2,24.6 19.574,36.974 ccw(c17.778,38.77) 20.318,38.77 20.318,43.64 ccw(c19.837,43.64) 20.177,43.98 cw(c20.297,44.1) v2(20.128,44.1)
S33_48.S48_N: P6.69 U16.H19 | length 59.9
  Top Layer w0.127: v1(-4,8) U16.H19@-3.5,7.5 ; P6.69@21.62,41.687 P6.69@21.62,42.515 21.62,43.344 cw(c21.858,43.344) 21.689,43.512 21.729,43.552 cw(c21.801,43.48) 21.801,43.582 ccw(c21.801,43.684) 21.873,43.612 ccw(c21.766,43.72) 21.918,43.72 ccw(c21.639,43.72) 21.836,43.917 21.78,43.973 cw(c21.907,44.1) v2(21.728,44.1)
  Int6 (Sign) w0.076: v1(-4,8) cw(c-4,7.602) -3.602,7.602 -3.602,6.998 ccw(c-3,6.998) -3,6.397 -1,6.397 ccw(c-1,8) 0.603,8 0.603,28.951 cw(c3.143,28.951) 1.347,30.747 14.656,44.056 cw(c16.452,42.26) 16.452,44.8 21.618,44.8 cw(c21.618,44.5) 21.918,44.5 21.918,44.291 cw(c21.728,44.291) v2(21.728,44.1)
S33_48.S48_P: P6.71 U16.J19 | length 59.9
  Top Layer w0.127: v1(-3,8) U16.J19@-2.5,7.5 ; v2(22.312,44.1) cw(c22.132,44.1) 22.259,43.973 22.203,43.917 ccw(c22.4,43.72) 22.121,43.72 ccw(c22.273,43.72) 22.166,43.612 ccw(c22.238,43.684) 22.238,43.582 cw(c22.238,43.48) 22.31,43.552 22.35,43.512 cw(c22.181,43.344) 22.42,43.344 P6.71@22.42,42.515 P6.71@22.42,41.687
  Int6 (Sign) w0.076: v1(-3,8) ccw(c-3,7.602) -3.398,7.602 -3.398,6.998 ccw(c-3,6.998) -3,6.6 -1,6.6 ccw(c-1,8) 0.4,8 0.4,28.952 cw(c3.141,28.952) 1.203,30.89 14.513,44.2 cw(c16.451,42.263) 16.451,45.003 21.618,45.003 cw(c21.618,44.5) 22.121,44.5 22.121,44.291 ccw(c22.312,44.291) v2(22.312,44.1)
S49_64.S49_N: P6.12 U16.D19 | length 49.3
  Top Layer w0.127: v1(-8,8) U16.D19@-7.5,7.5 ; v2(-5.688,46.6) ccw(c-5.867,46.6) -5.74,46.727 -5.783,46.77 cw(c-5.553,47) -5.878,47 -5.878,47.04 cw(c-5.726,47.04) -5.833,47.148 cw(c-5.761,47.076) -5.761,47.178 ccw(c-5.761,47.28) -5.689,47.208 -5.649,47.248 ccw(c-5.818,47.416) -5.58,47.416 P6.12@-5.58,48.245
  Int2 (Sign) w0.076: v1(-8,8) ccw(c-8,8.398) -7.602,8.398 -7.602,39.162 ccw(c-10.142,39.162) -8.346,40.958 -10.049,42.662 cw(c-8.713,43.999) -10.603,43.999 -10.603,47 cw(c-9.5,47) -9.5,48.103 -6.961,48.103 cw(c-6.961,47.02) -5.878,47.02 -5.878,46.791 ccw(c-5.688,46.791) v2(-5.688,46.6)
S49_64.S49_P: P6.10 U16.E19 | length 48.7
  Top Layer w0.127: v1(-7,8) U16.E19@-6.5,7.5 ; P6.10@-6.38,48.245 -6.38,47.416 ccw(c-6.141,47.416) -6.31,47.248 -6.27,47.208 ccw(c-6.198,47.28) -6.198,47.178 cw(c-6.198,47.076) -6.126,47.148 cw(c-6.233,47.04) -6.081,47.04 -6.081,47 cw(c-6.406,47) -6.176,46.77 -6.219,46.727 ccw(c-6.092,46.6) v2(-6.272,46.6)
  Int2 (Sign) w0.076: v1(-7,8) cw(c-7,8.398) -7.398,8.398 -7.398,39.165 ccw(c-10.136,39.165) -8.2,41.1 -9.905,42.805 cw(c-8.71,44) -10.4,44 -10.4,47 cw(c-9.5,47) -9.5,47.9 -6.961,47.9 cw(c-6.961,47.02) -6.081,47.02 -6.081,46.791 cw(c-6.272,46.791) v2(-6.272,46.6)
S49_64.S50_N: P6.14 U16.F14 | length 51.3
  Top Layer w0.127: v1(-6,3) U16.F14@-5.5,2.5 ; P6.14@-4.78,48.245 -4.78,47.416 ccw(c-4.541,47.416) -4.71,47.248 -4.67,47.208 ccw(c-4.598,47.28) -4.598,47.178 cw(c-4.598,47.076) -4.526,47.148 cw(c-4.634,47.04) -4.481,47.04 -4.481,47.029 cw(c-4.807,47.029) -4.577,46.799 -4.619,46.756 ccw(c-4.492,46.629) v2(-4.672,46.629)
  Int7 (Sign) w0.076: v1(-6,3) -6,2.802 ccw(c-5.8,2.802) -5.8,2.602 ccw(c-5.8,2.802) -5.6,2.802 -5.6,3 ccw(c-6,3) -6,3.4 -8,3.4 cw(c-8,4.003) -8.603,4.003 -8.603,5.003 -8.603,37.1 -8.603,39.329 cw(c-5.863,39.329) -7.8,41.267 -5.225,43.842 ccw(c-7.021,45.638) -4.481,45.638 -4.481,46.169 ccw(c-4.963,46.169) -4.622,46.51 cw(c-4.503,46.629) v2(-4.672,46.629)
S49_64.S50_P: P6.16 U16.F13 | length 51.6
  Top Layer w0.127: v1(-6,2) U16.F13@-5.5,1.5 ; v2(-4.088,46.629) ccw(c-4.267,46.629) -4.14,46.756 -4.183,46.799 cw(c-3.953,47.029) -4.278,47.029 -4.278,47.04 cw(c-4.126,47.04) -4.234,47.148 cw(c-4.162,47.076) -4.162,47.178 ccw(c-4.162,47.28) -4.09,47.208 -4.05,47.248 ccw(c-4.218,47.416) -3.98,47.416 P6.16@-3.98,48.245
  Int7 (Sign) w0.076: v1(-6,2) -6,2.198 cw(c-5.8,2.198) -5.8,2.398 ccw(c-5.8,2.802) -5.397,2.802 -5.397,3 ccw(c-6,3) -6,3.603 -8,3.603 cw(c-8,4.003) -8.4,4.003 -8.4,5.003 -8.4,37.1 -8.4,39.328 cw(c-5.86,39.328) -7.656,41.124 -5.081,43.699 ccw(c-7.019,45.637) -4.278,45.637 -4.278,46.169 cw(c-3.797,46.169) -4.137,46.51 ccw(c-4.257,46.629) v2(-4.088,46.629)
S49_64.S51_N: P6.20 U16.G16 | length 48.9
  Top Layer w0.127: v1(-5,5) U16.G16@-4.5,4.5 ; v2(-2.488,46.608) ccw(c-2.667,46.608) -2.54,46.735 -2.583,46.777 cw(c-2.353,47.007) -2.678,47.007 -2.678,47.04 cw(c-2.526,47.04) -2.633,47.148 cw(c-2.561,47.076) -2.561,47.178 ccw(c-2.561,47.28) -2.489,47.208 -2.449,47.248 ccw(c-2.618,47.416) -2.38,47.416 P6.20@-2.38,48.245
  Int7 (Sign) w0.076: v1(-5,5) -5,4.802 cw(c-5.2,4.802) -5.2,4.602 -7,4.602 cw(c-7,5.002) -7.4,5.002 -7.4,39.289 cw(c-4.86,39.289) -6.656,41.085 -3.442,44.299 ccw(c-5.287,46.144) -2.678,46.144 -2.678,46.148 cw(c-2.197,46.148) -2.537,46.488 ccw(c-2.657,46.608) v2(-2.488,46.608)
S49_64.S51_P: P6.18 U16.G15 | length 49.2
  Top Layer w0.127: v1(-5,4) U16.G15@-4.5,3.5 ; P6.18@-3.18,48.245 -3.18,47.416 ccw(c-2.941,47.416) -3.11,47.248 -3.07,47.208 ccw(c-2.998,47.28) -2.998,47.178 cw(c-2.998,47.076) -2.926,47.148 cw(c-3.033,47.04) -2.881,47.04 -2.881,47.007 cw(c-3.206,47.007) -2.976,46.777 -3.019,46.735 ccw(c-2.892,46.608) v2(-3.072,46.608)
  Int7 (Sign) w0.076: v1(-5,4) -5,4.198 ccw(c-5.2,4.198) -5.2,4.398 -7,4.398 cw(c-7,5.002) -7.603,5.002 -7.603,39.29 cw(c-4.863,39.29) -6.8,41.228 -3.589,44.44 ccw(c-5.297,46.148) -2.881,46.148 ccw(c-3.363,46.148) -3.022,46.488 cw(c-2.903,46.608) v2(-3.072,46.608)
S49_64.S52_N: P6.22 U16.H14 | length 50.8
  Top Layer w0.127: v1(-4,3) U16.H14@-3.5,2.5 ; P6.22@-1.58,48.245 -1.58,47.416 ccw(c-1.341,47.416) -1.51,47.248 -1.47,47.208 ccw(c-1.398,47.28) -1.398,47.178 cw(c-1.398,47.076) -1.326,47.148 cw(c-1.434,47.04) -1.281,47.04 -1.281,47.007 cw(c-1.607,47.007) -1.377,46.777 -1.419,46.735 ccw(c-1.292,46.608) v2(-1.472,46.608)
  Int7 (Sign) w0.076: v1(-4,3) -3.802,3 ccw(c-3.802,3.2) -3.602,3.2 ccw(c-3.802,3.2) -3.802,3.4 -4.1,3.4 cw(c-4.1,3.903) -4.603,3.903 -4.603,5.003 ccw(c-5,5.003) -5,5.4 -6,5.4 cw(c-6,6.003) -6.603,6.003 -6.603,39.171 cw(c-3.863,39.171) -5.8,41.109 -1.649,45.261 ccw(c-2.536,46.148) -1.281,46.148 ccw(c-1.763,46.148) -1.422,46.488 cw(c-1.303,46.608) v2(-1.472,46.608)
S49_64.S52_P: P6.24 U16.J14 | length 50.8
  Top Layer w0.127: v1(-3,3) U16.J14@-2.5,2.5 ; v2(-0.888,46.608) ccw(c-1.067,46.608) -0.94,46.735 -0.983,46.777 cw(c-0.753,47.007) -1.078,47.007 -1.078,47.04 cw(c-0.926,47.04) -1.034,47.148 cw(c-0.962,47.076) -0.962,47.178 ccw(c-0.962,47.28) -0.89,47.208 -0.85,47.248 ccw(c-1.018,47.416) -0.78,47.416 P6.24@-0.78,48.245
  Int7 (Sign) w0.076: v1(-3,3) -3.198,3 cw(c-3.198,3.2) -3.398,3.2 ccw(c-3.802,3.2) -3.802,3.603 -4.1,3.603 cw(c-4.1,3.903) -4.4,3.903 -4.4,5.003 ccw(c-5,5.003) -5,5.603 -6,5.603 cw(c-6,6.003) -6.4,6.003 -6.4,39.17 cw(c-3.86,39.17) -5.656,40.966 -1.505,45.118 ccw(c-2.535,46.148) -1.078,46.148 cw(c-0.597,46.148) -0.937,46.488 ccw(c-1.057,46.608) v2(-0.888,46.608)
S49_64.S53_N: P6.28 U16.G18 | length 45.6
  Top Layer w0.127: v1(-5,7) U16.G18@-4.5,6.5 ; v2(0.712,46.6) ccw(c0.533,46.6) 0.66,46.727 0.617,46.77 cw(c0.847,47) 0.522,47 0.522,47.04 cw(c0.674,47.04) 0.566,47.148 cw(c0.638,47.076) 0.638,47.178 ccw(c0.638,47.28) 0.71,47.208 0.751,47.248 ccw(c0.582,47.416) 0.82,47.416 P6.28@0.82,48.245
  Int7 (Sign) w0.076: v1(-5,7) -5,6.802 cw(c-5.2,6.802) -5.2,6.602 cw(c-5.2,6.802) -5.4,6.802 -5.4,39.141 cw(c-2.86,39.141) -4.656,40.937 0.387,45.98 ccw(c0.06,46.306) 0.522,46.306 0.522,46.308 cw(c0.599,46.308) 0.544,46.362 0.663,46.48 ccw(c0.543,46.6) v2(0.712,46.6)
S49_64.S53_P: P6.26 U16.G17 | length 45.9
  Top Layer w0.127: v1(-5,6) U16.G17@-4.5,5.5 ; P6.26@0.02,48.245 0.02,47.416 ccw(c0.259,47.416) 0.09,47.248 0.13,47.208 ccw(c0.202,47.28) 0.202,47.178 cw(c0.202,47.076) 0.274,47.148 cw(c0.167,47.04) 0.319,47.04 0.319,47 cw(c-0.006,47) 0.223,46.77 0.181,46.727 ccw(c0.308,46.6) v2(0.128,46.6)
  Int7 (Sign) w0.076: v1(-5,6) -5,6.198 ccw(c-5.2,6.198) -5.2,6.398 cw(c-5.2,6.802) -5.603,6.802 -5.603,39.142 cw(c-2.863,39.142) -4.8,41.08 0.242,46.122 ccw(c0.056,46.308) 0.319,46.308 ccw(c0.242,46.308) 0.296,46.362 0.178,46.48 cw(c0.297,46.6) v2(0.128,46.6)
S49_64.S54_N: P6.30 U16.H18 | length 46.7
  Top Layer w0.127: v1(-4,7) U16.H18@-3.5,6.5 ; P6.30@1.62,48.245 1.62,47.416 ccw(c1.859,47.416) 1.69,47.248 1.73,47.208 ccw(c1.802,47.28) 1.802,47.178 cw(c1.802,47.076) 1.874,47.148 cw(c1.766,47.04) 1.919,47.04 1.919,47 cw(c1.593,47) 1.823,46.77 1.781,46.727 ccw(c1.908,46.6) v2(1.728,46.6)
  Int7 (Sign) w0.076: v1(-4,7) -4,6.802 ccw(c-3.802,6.801) -3.603,6.802 -3.603,10.497 ccw(c-4.342,10.497) -3.819,11.019 -4.001,11.201 cw(c-2.548,12.655) -4.603,12.655 -4.603,39.211 cw(c-1.863,39.211) -3.8,41.149 -3.736,41.213 -0.255,44.695 cw(c0.566,43.874) 0.566,45.035 0.813,45.035 ccw(c0.813,46.14) 1.919,46.14 ccw(c1.437,46.14) 1.778,46.48 cw(c1.897,46.6) v2(1.728,46.6)
S49_64.S54_P: P6.32 U16.H17 | length 47
  Top Layer w0.127: v1(-4,6) U16.H17@-3.5,5.5 ; v2(2.312,46.6) ccw(c2.133,46.6) 2.26,46.727 2.217,46.77 cw(c2.447,47) 2.122,47 2.122,47.04 cw(c2.274,47.04) 2.166,47.148 cw(c2.238,47.076) 2.238,47.178 ccw(c2.238,47.28) 2.31,47.208 2.35,47.248 ccw(c2.182,47.416) 2.42,47.416 P6.32@2.42,48.245
  Int7 (Sign) w0.076: v1(-4,6) -4,6.198 cw(c-3.8,6.198) -3.8,6.398 ccw(c-3.8,6.798) -3.4,6.798 -3.4,10.5 ccw(c-4.335,10.5) -3.674,11.161 -3.856,11.344 cw(c-2.544,12.656) -4.4,12.656 -4.4,39.21 cw(c-1.86,39.21) -3.656,41.006 -3.592,41.07 -0.17,44.491 cw(c0.651,43.67) 0.651,44.832 0.813,44.832 ccw(c0.813,46.14) 2.122,46.139 ; 2.122,46.14 cw(c2.603,46.14) 2.263,46.48 ccw(c2.143,46.6) v2(2.312,46.6)
S49_64.S55_N: P6.36 U16.K14 | length 50.3
  Top Layer w0.127: v1(-2,3) U16.K14@-1.5,2.5 ; v2(3.912,46.608) ccw(c3.733,46.608) 3.86,46.735 3.817,46.777 cw(c4.047,47.007) 3.722,47.007 3.722,47.04 cw(c3.874,47.04) 3.766,47.148 cw(c3.838,47.076) 3.838,47.178 ccw(c3.838,47.28) 3.91,47.208 3.951,47.248 ccw(c3.782,47.416) 4.02,47.416 P6.36@4.02,48.245
  Int7 (Sign) w0.076: v1(-2,3) -2,2.802 cw(c-2.2,2.802) -2.2,2.602 cw(c-2.2,2.802) -2.4,2.802 -2.4,10.502 ccw(c-3.812,10.502) -2.814,11.501 cw(c-1.398,12.917) -3.4,12.917 -3.4,37.434 cw(c-0.86,37.434) -2.656,39.23 3.463,45.348 ccw(c2.836,45.975) 3.722,45.975 3.722,46.148 cw(c4.203,46.148) 3.863,46.488 ccw(c3.743,46.608) v2(3.912,46.608)
S49_64.S55_P: P6.34 U16.K13 | length 50.6
  Top Layer w0.127: v1(-2,2) U16.K13@-1.5,1.5 ; P6.34@3.22,48.245 3.22,47.416 ccw(c3.459,47.416) 3.29,47.248 3.33,47.208 ccw(c3.402,47.28) 3.402,47.178 cw(c3.402,47.076) 3.474,47.148 cw(c3.367,47.04) 3.519,47.04 3.519,47.007 cw(c3.193,47.007) 3.423,46.777 3.381,46.735 ccw(c3.508,46.608) v2(3.328,46.608)
  Int7 (Sign) w0.076: v1(-2,2) -2,2.198 ccw(c-2.2,2.198) -2.2,2.398 cw(c-2.2,2.802) -2.603,2.802 -2.603,10.5 ccw(c-3.818,10.5) -2.959,11.359 -3,11.4 cw(c-1.544,12.856) -3.603,12.856 -3.603,37.435 cw(c-0.863,37.435) -2.8,39.373 3.301,45.474 ccw(c2.775,46) 3.519,46 3.519,46.148 ccw(c3.037,46.148) 3.378,46.488 cw(c3.497,46.608) v2(3.328,46.608)
S49_64.S56_N: P6.38 U16.J21 | length 44.4
  Top Layer w0.127: v1(-3,10) U16.J21@-2.5,9.5 ; P6.38@4.82,48.245 4.82,47.416 ccw(c5.059,47.416) 4.89,47.248 4.93,47.208 ccw(c5.002,47.28) 5.002,47.178 cw(c5.002,47.076) 5.074,47.148 cw(c4.966,47.04) 5.118,47.04 5.118,47 cw(c4.793,47) 5.023,46.77 4.981,46.727 ccw(c5.108,46.6) v2(4.928,46.6)
  Int6 (Sign) w0.076: v1(-3,10) -3,9.802 ccw(c-2.8,9.802) -2.8,9.602 ccw(c-2.8,9.802) -2.6,9.802 -2.6,31.552 cw(c0.141,31.552) -1.798,33.489 ; -1.797,33.49 6.055,41.342 ccw(c4.497,42.9) 6.7,42.9 6.7,43.6 ccw(c6.023,43.6) 6.502,44.079 5.509,45.072 cw(c6.451,46.014) 5.118,46.014 5.118,46.14 ccw(c4.637,46.14) 4.978,46.48 cw(c5.097,46.6) v2(4.928,46.6)
S49_64.S56_P: P6.40 U16.J20 | length 44.8
  Top Layer w0.127: v1(-3,9) U16.J20@-2.5,8.5 ; v2(5.512,46.6) ccw(c5.333,46.6) 5.46,46.727 5.417,46.77 cw(c5.647,47) 5.322,47 5.322,47.04 cw(c5.474,47.04) 5.366,47.148 cw(c5.438,47.076) 5.438,47.178 ccw(c5.438,47.28) 5.51,47.208 5.55,47.248 ccw(c5.382,47.416) 5.62,47.416 P6.40@5.62,48.245
  Int6 (Sign) w0.076: v1(-3,9) -3,9.198 cw(c-2.8,9.198) -2.8,9.398 ccw(c-2.8,9.802) -2.397,9.802 -2.397,31.551 cw(c0.143,31.551) -1.653,33.347 6.201,41.201 ccw(c4.506,42.896) 6.903,42.896 6.903,43.602 ccw(c6.027,43.602) 6.647,44.221 5.696,45.172 ; v2(5.512,46.6) cw(c5.343,46.6) 5.463,46.48 ccw(c5.803,46.14) 5.322,46.14 5.322,46.015 ccw(c6.453,46.015) 5.653,45.215 5.696,45.172
S49_64.S57_N: P6.44 U16.L20 | length 47
  Top Layer w0.127: v1(-1,9) U16.L20@-0.5,8.5 ; v2(11.112,46.6) ccw(c10.932,46.6) 11.059,46.727 11.017,46.77 cw(c11.247,47) 10.922,47 10.922,47.04 cw(c11.074,47.04) 10.966,47.148 cw(c11.038,47.076) 11.038,47.178 ccw(c11.038,47.28) 11.11,47.208 11.15,47.248 ccw(c10.981,47.416) 11.22,47.416 P6.44@11.22,48.245
  Int6 (Sign) w0.076: v1(-1,9) -1,8.802 cw(c-1.2,8.802) -1.2,8.602 cw(c-1.2,8.802) -1.4,8.802 -1.4,30.748 cw(c1.14,30.748) -0.656,32.544 7.098,40.298 ccw(c5.16,42.236) 7.9,42.236 7.9,43.974 cw(c9.4,43.974) 9.4,45.473 10.295,45.473 ccw(c10.295,46.1) 10.922,46.1 10.922,46.2 cw(c11.258,46.2) 11.02,46.438 11.063,46.48 ccw(c10.943,46.6) v2(11.112,46.6)
S49_64.S57_P: P6.42 U16.L19 | length 47.3
  Top Layer w0.127: v1(-1,8) U16.L19@-0.5,7.5 ; P6.42@10.42,48.245 10.42,47.416 ccw(c10.658,47.416) 10.49,47.248 10.53,47.208 ccw(c10.602,47.28) 10.602,47.178 cw(c10.602,47.076) 10.674,47.148 cw(c10.566,47.04) 10.718,47.04 10.718,47 cw(c10.393,47) 10.623,46.77 10.58,46.727 ccw(c10.707,46.6) v2(10.528,46.6)
  Int6 (Sign) w0.076: v1(-1,8) -1,8.198 ccw(c-1.2,8.198) -1.2,8.398 cw(c-1.2,8.802) -1.603,8.802 -1.603,30.749 cw(c1.137,30.749) -0.801,32.686 ; -0.8,32.687 6.953,40.441 ccw(c5.157,42.237) 7.697,42.237 7.697,43.974 cw(c9.4,43.974) 9.4,45.676 10.295,45.676 ccw(c10.295,46.1) 10.718,46.1 10.718,46.2 ccw(c10.382,46.2) 10.62,46.438 10.577,46.48 cw(c10.697,46.6) v2(10.528,46.6)
S49_64.S58_N: P6.46 U16.E17 | length 58.6
  Top Layer w0.127: v1(-7,6) U16.E17@-6.5,5.5 ; P6.46@12.02,48.245 12.02,47.416 ccw(c12.258,47.416) 12.09,47.248 12.13,47.208 ccw(c12.202,47.28) 12.202,47.178 cw(c12.202,47.076) 12.274,47.148 cw(c12.166,47.04) 12.318,47.04 12.318,47 cw(c11.993,47) 12.223,46.77 12.18,46.727 ccw(c12.307,46.6) v2(12.128,46.6)
  Int2 (Sign) w0.076: v1(-7,6) -6.425,6 ccw(c-6.425,6.076) -6.35,6.063 cw(c-6,6) -6,6.356 ccw(c-6,6.869) -5.637,6.506 cw(c-5.402,6.271) -5.402,6.603 -5,6.603 cw(c-5,6.003) -4.4,6.003 -4.4,5 ccw(c-4,5) -4,4.6 -1,4.6 ccw(c-1,5) -0.6,5 -0.6,26.465 cw(c2.141,26.465) 0.203,28.403 12.976,41.176 ccw(c11.951,42.2) 13.4,42.197 ccw(c11.951,42.2) 13.4,42.2 13.4,43.5 ccw(c11.438,43.5) 12.825,44.887 12.661,45.052 cw(c13.489,45.879) 12.318,45.879 12.318,46.14 ccw(c11.837,46.14) 12.177,46.48 cw(c12.297,46.6) v2(12.128,46.6)
S49_64.S58_P: P6.48 U16.F16 | length 58.7
  Top Layer w0.127: v1@-5.998,5.002 -5.5,4.505 U16.F16@-5.5,4.5 ; v2(12.712,46.6) ccw(c12.532,46.6) 12.659,46.727 12.617,46.77 cw(c12.847,47) 12.521,47 12.521,47.04 cw(c12.673,47.04) 12.566,47.148 cw(c12.638,47.076) 12.638,47.178 ccw(c12.638,47.28) 12.71,47.208 12.75,47.248 ccw(c12.581,47.416) 12.82,47.416 P6.48@12.82,48.245
  Int2 (Sign) w0.076: v1(-6,5) -6,5.575 cw(c-5.924,5.575) -5.938,5.65 ccw(c-6,6) -5.644,5.998 cw(c-5.131,5.998) -5.494,6.361 cw(c-5.401,6.268) -5.401,6.4 -5,6.4 cw(c-5,6.003) -4.603,6.003 -4.603,5 ccw(c-4,5) -4,4.397 -1,4.397 ccw(c-1,5) -0.397,5 -0.397,26.464 cw(c2.143,26.464) 0.347,28.26 13.122,41.035 ccw(c11.961,42.196) 13.603,42.196 13.603,43.503 ccw(c11.445,43.503) 12.971,45.029 12.812,45.188 cw(c13.515,45.89) 12.521,45.89 12.521,46.14 cw(c13.003,46.14) 12.662,46.48 ccw(c12.543,46.6) v2(12.712,46.6)
S49_64.S59_N: P6.52 U16.M16 | length 50.9
  Top Layer w0.127: U16.M16@0.5,4.5 v1(1,5) ; v2(14.312,46.6) ccw(c14.132,46.6) 14.259,46.727 14.217,46.77 cw(c14.447,47) 14.122,47 14.122,47.04 cw(c14.274,47.04) 14.166,47.148 cw(c14.238,47.076) 14.238,47.178 ccw(c14.238,47.28) 14.31,47.208 14.35,47.248 ccw(c14.181,47.416) 14.42,47.416 P6.52@14.42,48.245
  Int2 (Sign) w0.076: v1(1,5) 1,4.795 cw(c0.807,4.795) 0.807,4.602 cw(c0.807,4.809) 0.6,4.809 0.6,25.861 cw(c3.14,25.861) 1.344,27.657 14.014,40.327 ccw(c12.841,41.5) 14.5,41.5 14.5,44.81 ccw(c13.799,44.81) 14.295,45.305 14.2,45.4 cw(c14.39,45.59) 14.122,45.59 14.122,46.14 cw(c14.603,46.14) 14.262,46.48 ccw(c14.143,46.6) v2(14.312,46.6)
S49_64.S59_P: P6.50 U16.M15 | length 51.2
  Top Layer w0.127: U16.M15@0.5,3.5 v1(1,4) ; P6.50@13.62,48.245 13.62,47.416 ccw(c13.858,47.416) 13.69,47.248 13.73,47.208 ccw(c13.802,47.28) 13.802,47.178 cw(c13.802,47.076) 13.874,47.148 cw(c13.766,47.04) 13.918,47.04 13.918,47 cw(c13.593,47) 13.823,46.77 13.78,46.727 ccw(c13.907,46.6) v2(13.728,46.6)
  Int2 (Sign) w0.076: v1(1,4) 1,4.205 ccw(c0.807,4.205) 0.807,4.398 cw(c0.807,4.809) 0.397,4.809 0.397,25.862 cw(c3.137,25.862) 1.2,27.8 13.87,40.47 ccw(c12.841,41.5) 14.297,41.5 14.297,44.809 ccw(c13.797,44.809) 14.15,45.162 14.056,45.257 cw(c14.387,45.588) 13.918,45.588 13.918,46.14 ccw(c13.437,46.14) 13.777,46.48 cw(c13.897,46.6) v2(13.728,46.6)
S49_64.S60_N: P6.54 U16.M20 | length 46
  Top Layer w0.127: U16.M20@0.5,8.5 v1(1,9) ; P6.54@15.22,48.245 15.22,47.416 ccw(c15.458,47.416) 15.289,47.248 15.33,47.208 ccw(c15.402,47.28) 15.402,47.178 cw(c15.402,47.076) 15.474,47.148 cw(c15.366,47.04) 15.518,47.04 15.518,47 cw(c15.193,47) 15.423,46.77 15.38,46.727 ccw(c15.507,46.6) v2(15.328,46.6)
  Int2 (Sign) w0.076: v1(1,9) ccw(c1,9.398) 1.398,9.398 1.398,23.798 1.397,23.8 1.397,25.362 cw(c4.137,25.362) 2.2,27.3 14.534,39.634 ccw(c13.169,41) 15.1,41 15.1,43.5 15.1,44.726 cw(c15.973,44.726) 15.356,45.343 ; v2(15.328,46.6) ccw(c15.497,46.6) 15.377,46.48 cw(c15.037,46.14) 15.518,46.14 15.518,45.734 ; 15.356,45.344 ccw(c14.966,45.734) 15.518,45.734 ; 15.518,45.716 15.518,45.734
